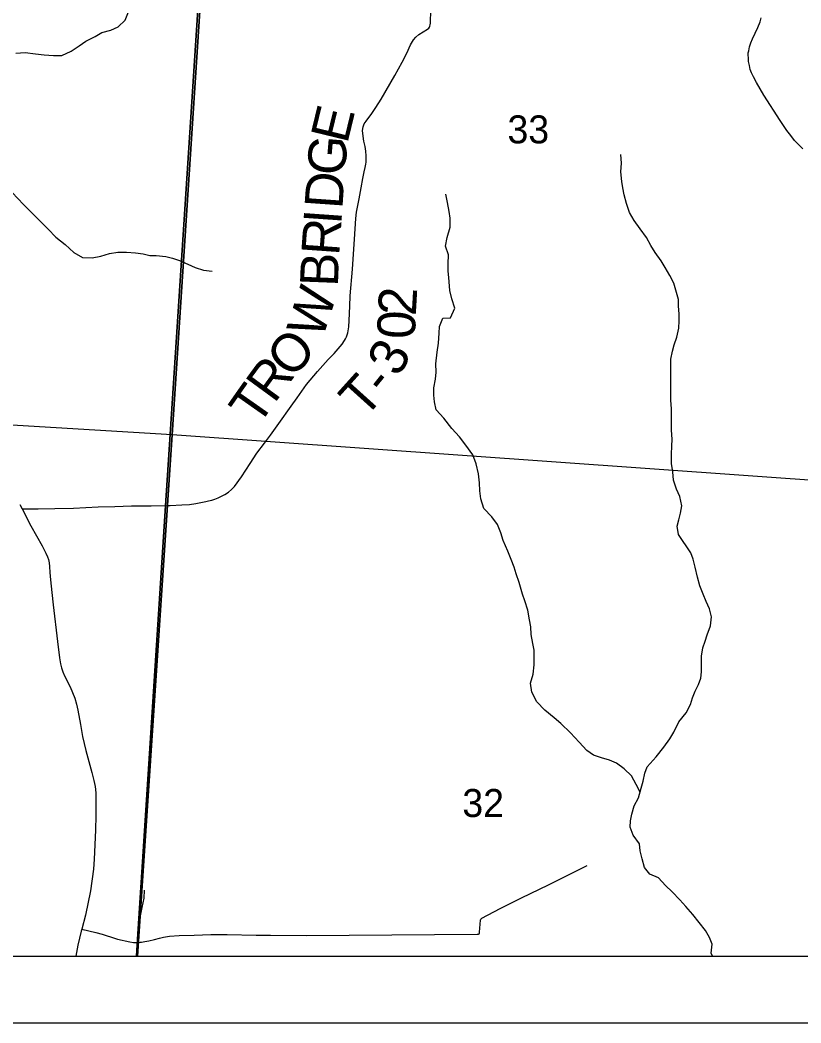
# Model space of a CAD drawing. Extents: x 0 to 34, y 0 to 22.
# Drawn here: x 3.016 to 4.184, y 14 to 15.5 of the extents above; entities that cross this region are included whole.
import ezdxf

# ---------------------------------------------------------------- set-up
doc = ezdxf.new("R2010")
doc.units = 0
for name, color, linetype in [('GM_X_Corporation', 7, 'Continuous'), ('GM_X_County_Road', 7, 'Continuous'), ('GM_X_Minor_River', 7, 'Continuous'), ('GM_X_Section_Text', 7, 'Continuous'), ('GM_X_Township_Road', 7, 'Continuous'), ('GM_X_Township_Road_Text', 7, 'Continuous'), ('GM_X_Township_Text', 7, 'Continuous'), ('SH_Data', 7, 'Continuous')]:
    doc.layers.add(name, color=color, linetype=linetype)

msp = doc.modelspace()

# ---------------------------------------------------------------- linework, layer by layer
at = {"layer": 'GM_X_Corporation'}
for points in [[(2.1, 19.0816), (2.1, 14.1), (3.1902, 14.1), (3.1919, 14.1255), (3.2339, 14.7735), (3.2844, 15.554), (3.3059, 15.8844), (3.3516, 16.5898), (3.3951, 17.2616), (3.507, 18.9883), (2.9513, 19.0267), (2.509, 19.0572), (2.4972, 19.0545), (2.4649, 19.0567)], [(2.2939, 15.964), (3.3089, 15.8803), (3.2437, 14.8797), (2.2272, 14.9411)], [(3.3089, 15.8803), (3.31, 15.8916), (4.31, 15.819), (4.245, 14.8084), (3.2437, 14.8797)], [(2.1881, 14.1), (3.1916, 14.1), (3.2437, 14.8797), (2.2272, 14.9411)], [(3.1916, 14.1), (4.1967, 14.1), (4.245, 14.8084), (3.2437, 14.8797)]]:
    msp.add_lwpolyline(points, close=True, dxfattribs=at)
at = {"layer": 'GM_X_County_Road'}
msp.add_lwpolyline([(3.0156, 14.7753), (3.0192, 14.7687), (3.0324, 14.7436), (3.0491, 14.7136), (3.0547, 14.7026), (3.0571, 14.697), (3.0586, 14.693), (3.0597, 14.688), (3.06, 14.6828), (3.0607, 14.6738), (3.0617, 14.6627), (3.0635, 14.6437), (3.0657, 14.6252), (3.072, 14.5707), (3.0751, 14.5461), (3.0767, 14.5369), (3.0782, 14.5309), (3.0802, 14.525), (3.0826, 14.5192), (3.0909, 14.5026), (3.0947, 14.4942), (3.0979, 14.4855), (3.1006, 14.4766), (3.1027, 14.4676), (3.1065, 14.4462), (3.1098, 14.4282), (3.1147, 14.4074), (3.1234, 14.3745), (3.1265, 14.3625), (3.1283, 14.3534), (3.1293, 14.3443), (3.1295, 14.3381), (3.1296, 14.3266), (3.1296, 14.3102), (3.1291, 14.2885), (3.1271, 14.2451), (3.1258, 14.23), (3.1213, 14.1978), (3.1138, 14.1611), (3.1084, 14.1403), (3.1076, 14.1372), (3.1026, 14.1161), (3.0994, 14.1)], dxfattribs=at)
at = {"layer": 'GM_X_Minor_River'}
for p, q in [((3.0046, 15.2418), (3.0213, 15.224)), ((3.6553, 15.2269), (3.6529, 15.2394)), ((3.658, 15.2136), (3.6553, 15.2269)), ((3.0213, 15.224), (3.0582, 15.1874)), ((3.6595, 15.2034), (3.658, 15.2136)), ((3.6592, 15.1901), (3.6595, 15.2034)), ((3.0582, 15.1874), (3.0699, 15.1753)), ((3.6551, 15.1749), (3.6592, 15.1901)), ((3.0699, 15.1753), (3.0836, 15.1644)), ((3.0836, 15.1644), (3.0965, 15.1523)), ((3.6525, 15.1617), (3.6551, 15.1749)), ((3.0965, 15.1523), (3.1094, 15.1448)), ((3.137, 15.1468), (3.1499, 15.1507)), ((3.1499, 15.1507), (3.1624, 15.1526)), ((3.1624, 15.1526), (3.1752, 15.1527)), ((3.1752, 15.1527), (3.1889, 15.152)), ((3.1889, 15.152), (3.2002, 15.1502)), ((3.2002, 15.1502), (3.2101, 15.1479)), ((3.657, 15.1488), (3.6525, 15.1617)), ((3.1094, 15.1448), (3.1238, 15.1445)), ((3.1238, 15.1445), (3.137, 15.1468)), ((3.2101, 15.1479), (3.2199, 15.1476)), ((3.2199, 15.1476), (3.2343, 15.1461)), ((3.2343, 15.1461), (3.2442, 15.1439)), ((3.2442, 15.1439), (3.2544, 15.1402)), ((3.2544, 15.1402), (3.2673, 15.1349)), ((3.2673, 15.1349), (3.2779, 15.13)), ((3.6563, 15.1351), (3.657, 15.1488)), ((3.6564, 15.1245), (3.6563, 15.1351)), ((3.2779, 15.13), (3.2904, 15.1259)), ((3.2904, 15.1259), (3.3033, 15.1245)), ((3.6572, 15.1151), (3.6564, 15.1245)), ((3.6588, 15.0954), (3.6572, 15.1151)), ((3.6618, 15.0829), (3.6588, 15.0954)), ((3.6664, 15.0689), (3.6618, 15.0829)), ((3.66, 15.0548), (3.6664, 15.0689)), ((3.6434, 15.0415), (3.6483, 15.054)), ((3.6483, 15.054), (3.66, 15.0548)), ((3.642, 15.0168), (3.6427, 15.0316)), ((3.6427, 15.0316), (3.6434, 15.0415)), ((3.6401, 15.0032), (3.642, 15.0168)), ((3.6379, 14.9857), (3.6401, 15.0032)), ((3.6384, 14.9732), (3.6379, 14.9857)), ((3.6376, 14.963), (3.6384, 14.9732)), ((3.635, 14.9501), (3.6376, 14.963)), ((3.6351, 14.9391), (3.635, 14.9501)), ((3.6359, 14.9289), (3.6351, 14.9391)), ((3.6386, 14.9168), (3.6359, 14.9289)), ((3.65, 14.9047), (3.6386, 14.9168)), ((3.6621, 14.8892), (3.65, 14.9047)), ((3.6735, 14.8767), (3.6621, 14.8892)), ((3.683, 14.8643), (3.6735, 14.8767)), ((3.6933, 14.8495), (3.683, 14.8643)), ((3.6983, 14.8363), (3.6933, 14.8495)), ((3.7017, 14.8212), (3.6983, 14.8363)), ((3.7033, 14.8079), (3.7017, 14.8212)), ((3.7037, 14.7958), (3.7033, 14.8079)), ((3.7053, 14.7837), (3.7037, 14.7958)), ((3.7099, 14.7693), (3.7053, 14.7837)), ((3.7216, 14.7568), (3.7099, 14.7693)), ((3.73, 14.7455), (3.7216, 14.7568)), ((3.7353, 14.733), (3.73, 14.7455)), ((3.7388, 14.7213), (3.7353, 14.733)), ((3.7457, 14.7058), (3.7388, 14.7213)), ((3.7506, 14.6929), (3.7457, 14.7058)), ((3.7552, 14.6819), (3.7506, 14.6929)), ((3.7579, 14.6717), (3.7552, 14.6819)), ((3.7625, 14.6585), (3.7579, 14.6717)), ((3.7675, 14.6411), (3.7625, 14.6585)), ((3.7709, 14.6312), (3.7675, 14.6411)), ((3.7755, 14.6172), (3.7709, 14.6312)), ((3.7782, 14.6028), (3.7755, 14.6172)), ((3.7801, 14.5922), (3.7782, 14.6028)), ((3.7805, 14.5812), (3.7801, 14.5922)), ((3.7832, 14.5676), (3.7805, 14.5812)), ((3.7848, 14.5574), (3.7832, 14.5676)), ((3.7852, 14.5456), (3.7848, 14.5574)), ((3.7834, 14.5217), (3.7849, 14.5358)), ((3.7849, 14.5358), (3.7852, 14.5456)), ((3.7797, 14.5081), (3.7834, 14.5217)), ((3.7816, 14.4948), (3.7797, 14.5081)), ((3.7888, 14.4801), (3.7816, 14.4948)), ((3.801, 14.468), (3.7888, 14.4801)), ((3.815, 14.4563), (3.801, 14.468)), ((3.8249, 14.4476), (3.815, 14.4563)), ((3.8393, 14.4341), (3.8249, 14.4476)), ((3.8523, 14.4201), (3.8393, 14.4341)), ((3.8637, 14.4076), (3.8523, 14.4201)), ((3.8735, 14.4005), (3.8637, 14.4076)), ((3.8856, 14.3964), (3.8735, 14.4005)), ((3.8978, 14.393), (3.8856, 14.3964)), ((3.908, 14.3885), (3.8978, 14.393)), ((3.9198, 14.3802), (3.908, 14.3885)), ((3.9308, 14.3697), (3.9198, 14.3802)), ((3.9376, 14.3564), (3.9308, 14.3697)), ((3.9435, 14.3451), (3.9376, 14.3564))]:
    msp.add_line(p, q, dxfattribs=at)
for points in [[(3.0099, 15.4502), (3.0239, 15.4514), (3.0391, 15.4496), (3.052, 15.4481), (3.066, 15.4467), (3.0788, 15.4471), (3.0924, 15.4536), (3.1045, 15.4616), (3.1143, 15.4685), (3.1287, 15.4754), (3.1385, 15.4811), (3.1521, 15.4846), (3.1627, 15.4896), (3.1736, 15.4998), (3.1781, 15.5124)], [(3.9674, 14.3982), (3.9787, 14.4123), (3.9877, 14.4249), (3.9941, 14.4348), (4.0013, 14.4503), (4.0122, 14.4636), (4.0186, 14.4765), (4.022, 14.486), (4.0257, 14.4963), (4.0306, 14.5062), (4.034, 14.5157), (4.0354, 14.5251), (4.0354, 14.5361), (4.035, 14.5486), (4.0372, 14.5608), (4.0406, 14.571), (4.0436, 14.5805), (4.0485, 14.5938), (4.0503, 14.6074), (4.0472, 14.6192), (4.0423, 14.6305), (4.0377, 14.6411), (4.0327, 14.6536), (4.0293, 14.6669), (4.0258, 14.6816), (4.0227, 14.6934), (4.0193, 14.7032), (4.001, 14.7304), (3.9987, 14.7429), (4.0013, 14.7524), (4.004, 14.7623), (4.0058, 14.7736), (4.0027, 14.7876), (3.9981, 14.7982), (3.9936, 14.8119), (3.9924, 14.8244), (3.9904, 14.8369), (3.9904, 14.8509), (3.9911, 14.8626), (3.9915, 14.8732), (3.9903, 14.8865), (3.9902, 14.8967), (3.9906, 14.9077), (3.9905, 14.9183), (3.9894, 14.9316), (3.9893, 14.9562), (3.9892, 14.9684), (3.9892, 14.9813), (3.9895, 14.9926), (3.9921, 15.0048), (3.9944, 15.0142), (3.9985, 15.0256), (4.0011, 15.0389), (4.0018, 15.0503), (4.0018, 15.0601), (4.001, 15.0723), (4.0006, 15.0821), (3.9979, 15.0927), (3.9937, 15.1063), (3.9879, 15.1177), (3.9811, 15.1298), (3.975, 15.1396), (3.9662, 15.1521), (3.9594, 15.1627), (3.9529, 15.1748), (3.9434, 15.1876), (3.9347, 15.2001), (3.9274, 15.2122), (3.9232, 15.2258), (3.9198, 15.2387), (3.9175, 15.2489), (3.9159, 15.2587), (3.9147, 15.2731), (3.9154, 15.286), (3.9146, 15.2989)], [(4.0515, 14.1), (4.0498, 14.1045), (4.0513, 14.1178), (4.0474, 14.128), (4.041, 14.1382), (4.0319, 14.1503), (4.0223, 14.162), (4.0117, 14.1741), (4.003, 14.1839), (3.9912, 14.196), (3.9813, 14.2058), (3.9707, 14.2171), (3.9582, 14.2227), (3.9502, 14.2325), (3.9464, 14.2454), (3.9437, 14.2575), (3.9425, 14.2681), (3.933, 14.281), (3.9288, 14.2927), (3.9291, 14.3022), (3.931, 14.312), (3.9347, 14.3246), (3.9411, 14.3367), (3.9452, 14.3512), (3.9478, 14.3614), (3.9504, 14.3735), (3.9542, 14.383), (3.9674, 14.3982)], [(3.1911, 14.1), (3.1918, 14.1124), (3.1932, 14.1261), (3.1943, 14.1393), (3.1954, 14.1492), (3.1965, 14.1602), (3.1988, 14.1727), (3.2017, 14.1864), (3.2025, 14.1985)]]:
    msp.add_lwpolyline(points, dxfattribs=at)
at = {"layer": 'GM_X_Township_Road'}
for points in [[(3.2381, 14.7739), (3.2405, 14.774), (3.258, 14.7747), (3.2698, 14.7754), (3.2789, 14.7767), (3.2941, 14.7797), (3.2982, 14.7807), (3.3032, 14.782), (3.3074, 14.7835), (3.3124, 14.7854), (3.3184, 14.7881), (3.3226, 14.7903), (3.3279, 14.794), (3.3325, 14.7979), (3.3369, 14.8025), (3.3472, 14.8169), (3.3603, 14.8369), (3.3705, 14.8521), (3.3815, 14.8669), (3.3909, 14.8789), (3.4031, 14.8966), (3.4218, 14.9224), (3.4305, 14.9348), (3.4444, 14.9551), (3.4608, 14.9742), (3.477, 14.9924), (3.4858, 15.0012), (3.4921, 15.0081), (3.4979, 15.0154), (3.5013, 15.0205), (3.5029, 15.0232), (3.5042, 15.0261), (3.5053, 15.029), (3.5061, 15.0319), (3.5068, 15.035), (3.5077, 15.0411), (3.5083, 15.0504), (3.5092, 15.0721), (3.51, 15.0876), (3.5135, 15.1275), (3.5161, 15.1723), (3.5184, 15.2033), (3.5194, 15.2125), (3.5231, 15.2325), (3.5262, 15.2489), (3.5288, 15.2632), (3.5307, 15.2729), (3.5321, 15.2795), (3.5331, 15.2844), (3.5336, 15.2872), (3.5339, 15.2902), (3.5339, 15.2969), (3.5333, 15.3039), (3.5323, 15.3106), (3.5305, 15.3187), (3.5288, 15.3301), (3.5285, 15.3347), (3.5293, 15.3402), (3.5308, 15.3445), (3.5337, 15.3487), (3.5421, 15.3603), (3.5464, 15.3663), (3.5481, 15.3689), (3.556, 15.3815), (3.5767, 15.4168), (3.5877, 15.437), (3.5944, 15.4502), (3.6002, 15.4627), (3.6046, 15.4702), (3.6078, 15.4742), (3.6125, 15.4785), (3.6189, 15.4823), (3.6255, 15.4861), (3.6273, 15.4876), (3.6284, 15.4891), (3.6291, 15.491), (3.6296, 15.493), (3.6298, 15.4954), (3.6301, 15.4995), (3.6304, 15.511)], [(4.1867, 15.3075), (4.1806, 15.3133), (4.1744, 15.32), (4.1686, 15.3271), (4.1629, 15.3347), (4.1527, 15.3495), (4.1283, 15.3875), (4.1173, 15.4065), (4.1129, 15.4148), (4.1102, 15.4208), (4.1082, 15.4261), (4.1068, 15.4322), (4.1057, 15.438), (4.1053, 15.4431), (4.105, 15.4479), (4.1052, 15.451), (4.1058, 15.4541), (4.1072, 15.4601), (4.1092, 15.466), (4.1116, 15.4717), (4.1157, 15.4801), (4.1197, 15.4886), (4.1231, 15.4973), (4.1246, 15.503)], [(3.0192, 14.7687), (3.0223, 14.7688), (3.0311, 14.7691), (3.0433, 14.7691), (3.0681, 14.7694), (3.096, 14.7701), (3.1331, 14.7718), (3.1579, 14.7726), (3.1827, 14.7732), (3.2123, 14.7735), (3.2369, 14.7739), (3.2381, 14.7739)], [(3.4446, 14.1308), (3.6997, 14.1327), (3.7018, 14.1329), (3.7024, 14.1331), (3.7028, 14.1334), (3.7031, 14.1341), (3.7034, 14.1356), (3.7045, 14.1538), (3.7053, 14.1552), (3.7068, 14.1565), (3.7344, 14.1712), (3.7663, 14.1869), (3.8064, 14.2065), (3.8643, 14.2357)], [(3.1084, 14.1403), (3.1293, 14.1351), (3.139, 14.1327), (3.1588, 14.1265), (3.1618, 14.1255), (3.1801, 14.1212), (3.1859, 14.1203), (3.1914, 14.1201), (3.1935, 14.1204), (3.1956, 14.1206)], [(3.1956, 14.1206), (3.1978, 14.1209), (3.2028, 14.1216), (3.2089, 14.1228), (3.2171, 14.1249), (3.2247, 14.127), (3.2309, 14.1284), (3.2395, 14.1296), (3.254, 14.1308), (3.2765, 14.1315), (3.3013, 14.1321), (3.3241, 14.1322)], [(3.3241, 14.1322), (3.326, 14.1322), (3.3692, 14.1314), (3.3907, 14.1314), (3.4446, 14.1308)]]:
    msp.add_lwpolyline(points, dxfattribs=at)
at = {"layer": 'GM_X_Township_Text'}
msp.add_lwpolyline([(8.9, 18.631), (7.8353, 18.6952), (7.8088, 18.6965), (7.389, 18.725), (7.0845, 18.7457), (7.0714, 18.7466), (7.0255, 18.7497), (6.895, 18.7585), (6.4706, 18.7873), (5.6003, 18.8464), (4.4362, 18.9253), (4.421, 18.9263), (4.2931, 18.935), (3.507, 18.9883), (3.3951, 17.2616), (3.3516, 16.5898), (3.3059, 15.8844), (3.2844, 15.554), (3.2339, 14.7735), (3.1919, 14.1255), (3.1902, 14.1)], dxfattribs=at)
at = {"layer": 'SH_Data'}
for p, q in [((2.1, 14.1), (8.9, 14.1)), ((2, 14), (9, 14))]:
    msp.add_line(p, q, dxfattribs=at)

# ---------------------------------------------------------------- texts
at = {"layer": 'GM_X_Section_Text'}
for s, p in [('33', (3.7451, 15.3155)), ('32', (3.6776, 14.308))]:
    msp.add_text(s, height=0.04186, rotation=0, dxfattribs=at).set_placement(p)
at = {"layer": 'GM_X_Township_Road_Text'}
for s, rotation, p in [('E', 76.3899, (3.5054, 15.3137)), ('G', 85.237, (3.5016, 15.2662)), ('D', 86.0064, (3.4981, 15.2165)), ('I', 86, (3.4965, 15.1932)), ('R', 86.0078, (3.4933, 15.1467)), ('B', 87.7142, (3.4914, 15.1005)), ('W', 71.9262, (3.468, 15.0211)), ('2', 86.772, (3.6079, 15.0568)), ('0', 87.6706, (3.6065, 15.0221)), ('O', 49.1197, (3.4232, 14.962)), ('3', 61.743, (3.5826, 14.9645)), ('R', 53.7999, (3.3964, 14.9253)), ('T', 48.0106, (3.5311, 14.9025)), ('-', 51.2855, (3.5618, 14.9368)), ('T', 54.9406, (3.3721, 14.8907))]:
    msp.add_text(s, height=0.0568, rotation=rotation, dxfattribs=at).set_placement(p)

doc.saveas('drawing.dxf')
